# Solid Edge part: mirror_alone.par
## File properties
Author: Owner
Template: Iso Part.par
Last saved by: Lee
Revision: 34
Application: Solid Edge
Material: Silver
Face Style: Silver
Fill Style: ANSI31(Iron)
Virtual Style: Silver
Coef. of Thermal Exp: 1e-05
Thermal Conductivity: 419.0
Specific Heat: 234.0
Modulus of Elasticity: 75842327000.0
Poisson's Ratio: 0.38
Yield Stress: 303369308.0
Ultimate Stress: 344737850.0
Elongation: 0.0
Density: 1.050e+004 kg/m^3
Accuracy: 0.990
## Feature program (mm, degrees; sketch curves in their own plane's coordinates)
sketch for "unnamed RevolvedProtrusion 1" plane through (0, 0, 0) normal (0, -1, 0) x-axis (1, 0, 0)
  line (0, -86.784) -> (1000, -86.784)
  line (1000, -86.784) -> (1000, 641.7424)
  arc centre (0, 1100) radius 1100 from (0, 0) to (1000, 641.7424) ccw
  line (0, 0) -> (0, -86.784)
revolve "unnamed RevolvedProtrusion 1" add full turn 360 deg
thinwall "Thinwall_1"  Thickness = 3 mm
sketch for "unnamed Cutout 1" #1 plane through (0, 0, -86.784) normal (0, 0, -1) x-axis (-1, 0, 0)
  line (300, 275) -> (300, -275)
  line (300, -275) -> (-300, -275)
  line (-300, -275) -> (-300, 275)
  line (-300, 275) -> (300, 275)
sketch for "unnamed Cutout 1" #2 plane through (0, 0, -86.784) normal (0, 0, -1) x-axis (-1, 0, 0)
  circle centre (0, 0) radius 1152.023
extrude "unnamed Cutout 1" cut finite 850 along -normal
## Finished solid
Body 1: solid body, 6 faces, 12 edges, 8 vertices.
  Faces by surface: plane 4, sphere 2
  Edges by curve: circle 8, line 4
Bounding box of the edges (mm; curved faces can reach further): 600.000 x 550.000 x 46.222, from (-300, -275, 31.8315) to (300, 275, 78.0533).
Spherical faces by radius (mm): R1100 x1, R1103 x1
Planar faces by outward normal: +x 1, +y 1, -x 1, -y 1
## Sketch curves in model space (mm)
arc centre (-225, -225, 0) radius 20 from (-232.5, -206.4595, 0) through (-238.2724, -239.9614, 0) to (-206.4595, -232.5, 0)
line (-206.4595, -232.5, 0) -> (6.6589, -232.5, 0)
line (6.6589, -232.5, 0) -> (232.5, -6.6589, 0)
line (232.5, 206.4595, 0) -> (232.5, -6.6589, 0)
arc centre (225, 225, 0) radius 20 from (206.4595, 232.5, 0) through (239.9614, 238.2724, 0) to (232.5, 206.4595, 0)
line (-206.4595, 232.5, 0) -> (206.4595, 232.5, 0)
arc centre (-225, 225, 0) radius 20 from (-206.4595, 232.5, 0) through (-239.9614, 238.2724, 0) to (-232.5, 206.4595, 0)
line (-232.5, 206.4595, 0) -> (-232.5, -206.4595, 0)
arc centre (-225, -225, 0) radius 20 from (-206.4595, -217.5, 0) through (-210.8579, -210.8579, 0) to (-217.5, -206.4595, 0)
line (-206.4595, -217.5, 0) -> (0, -217.5, 0)
line (0, -217.5, 0) -> (217.5, 0, 0)
line (217.5, 206.4595, 0) -> (217.5, 0, 0)
arc centre (225, 225, 0) radius 20 from (206.4595, 217.5, 0) through (210.8579, 210.8579, 0) to (217.5, 206.4595, 0)
line (-206.4595, 217.5, 0) -> (206.4595, 217.5, 0)
arc centre (-225, 225, 0) radius 20 from (-206.4595, 217.5, 0) through (-210.8579, 210.8579, 0) to (-217.5, 206.4595, 0)
line (-217.5, 206.4595, 0) -> (-217.5, -206.4595, 0)
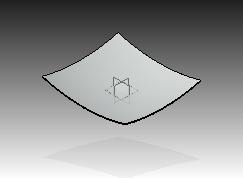
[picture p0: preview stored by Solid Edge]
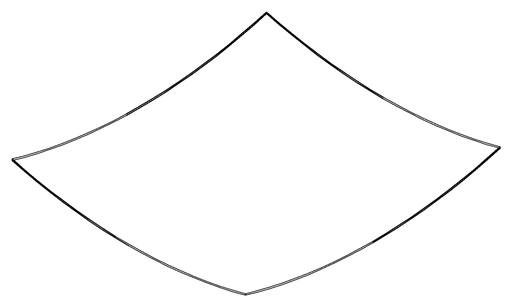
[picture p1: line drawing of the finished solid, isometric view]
